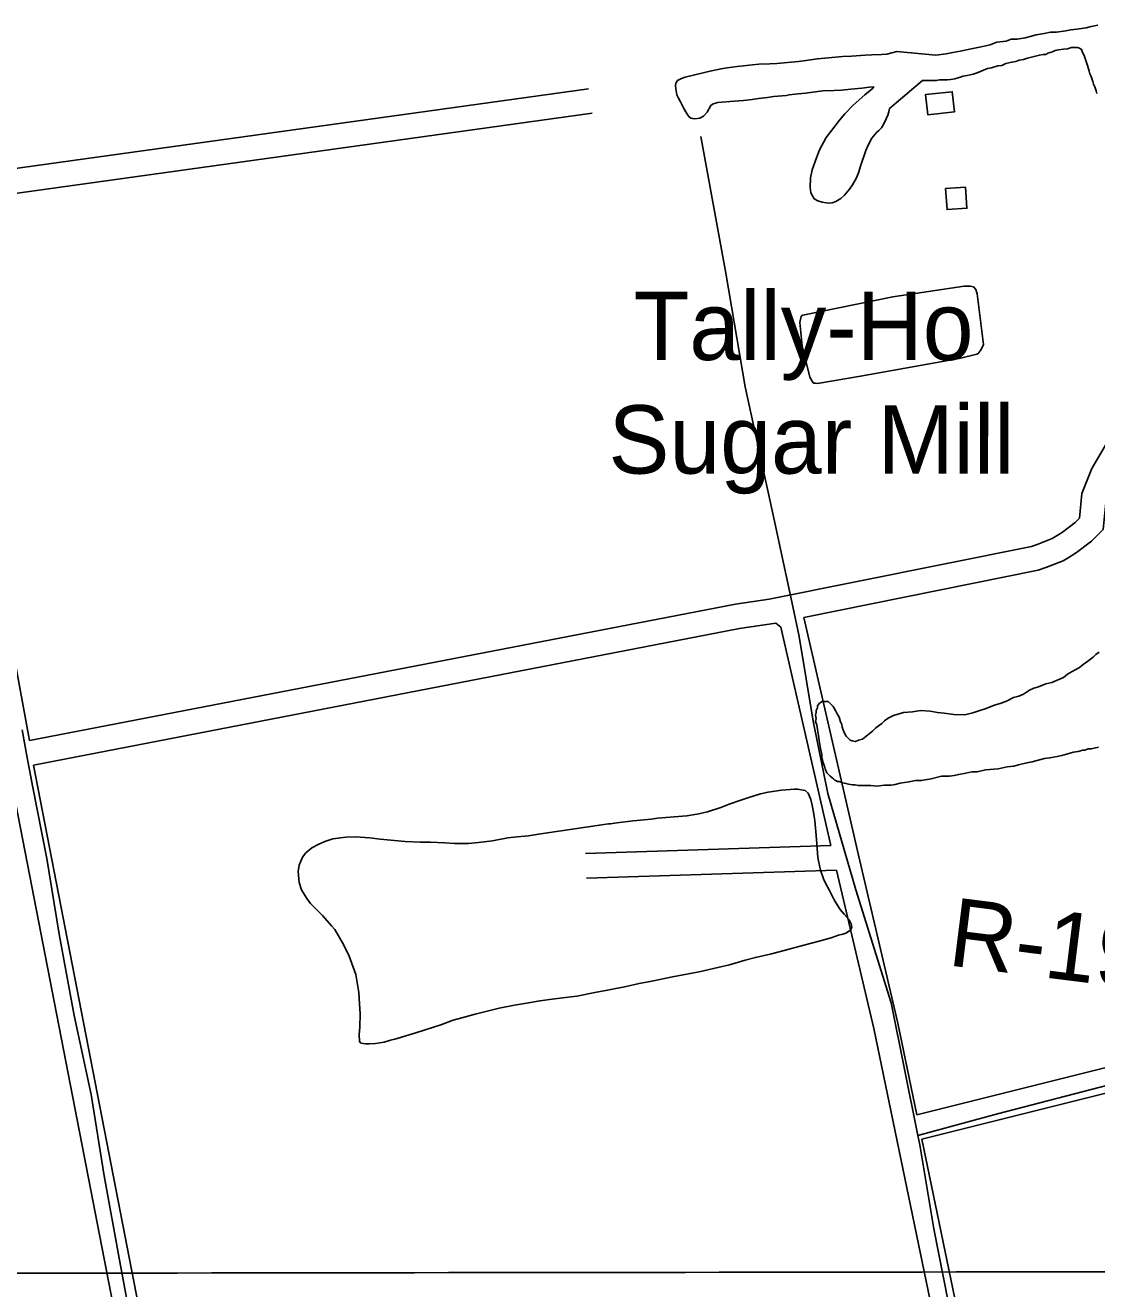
# Model space of a CAD drawing. Extents: x 3324125 to 3362000, y 600753 to 626151.
# Drawn here: x 3330131 to 3331432, y 618241 to 619776 of the extents above; entities that cross this region are included whole.
import ezdxf

# ---------------------------------------------------------------- set-up
doc = ezdxf.new("R2010")
doc.units = 0
for name, color, linetype in [('V-BLDG-IDEN', 7, 'Continuous'), ('V-BLDG-OTLN', 7, 'Continuous'), ('V-DTCH-CNTR', 7, 'Continuous'), ('V-GRID-MAJR', 7, 'Continuous'), ('V-RIVR-RANG-IDEN', 7, 'Continuous'), ('V-ROAD-CNTR', 7, 'Continuous'), ('V-SITE-VEGE', 7, 'Continuous'), ('V-TOPO-SHOR', 7, 'Continuous')]:
    doc.layers.add(name, color=color, linetype=linetype)

msp = doc.modelspace()

# ---------------------------------------------------------------- linework, layer by layer
at = {"layer": 'V-BLDG-OTLN'}
for points in [[(3331224.6, 619691.7), (3331257, 619695.1), (3331259.6, 619670.5), (3331227.2, 619667.1)], [(3331248.9, 619577.3), (3331273.1, 619578.9), (3331274.8, 619553.5), (3331250.7, 619551.8)]]:
    msp.add_lwpolyline(points, close=True, dxfattribs=at)
at = {"layer": 'V-DTCH-CNTR'}
for points in [[(3331258.3, 618192.4), (3331234.4, 618313.6), (3331217.5, 618415.7), (3331215.2, 618426.9), (3331182.8, 618587.9), (3331139.8, 618725.2), (3331105.6, 618842.5), (3331087.8, 618930.2), (3331070.9, 619033.1), (3331063.4, 619069.4), (3331040.2, 619177.1), (3331005.4, 619336.6), (3330981.6, 619474.6), (3330951.6, 619640.5)], [(3330126.9, 618919.7), (3330132.5, 618888.2), (3330139.8, 618849.5), (3330156.8, 618763.4), (3330171.7, 618671.3), (3330189.8, 618572.8), (3330210.7, 618476.7), (3330226.4, 618377.8), (3330245.6, 618273.4), (3330271.8, 618131.8), (3330298.4, 618004.6), (3330321.7, 617904.1), (3330351.9, 617768.1), (3330376.9, 617628.9), (3330397.7, 617531.6), (3330416.6, 617429.1), (3330430.7, 617337.1), (3330433, 617316.3), (3330443.5, 617274), (3330455.8, 617210.2), (3330473.6, 617123.7), (3330496.5, 617039.5), (3330502, 617020.8)], [(3331215.2, 618426.9), (3331311.8, 618453.3), (3331425.9, 618482.8), (3331525.6, 618508.5), (3331632.5, 618535.7), (3331741.9, 618566), (3331832, 618591.7), (3331966.9, 618626.7), (3332061.8, 618649.2)]]:
    msp.add_lwpolyline(points, dxfattribs=at)
at = {"layer": 'V-GRID-MAJR'}
msp.add_spline([(3328217.9, 618256.9), (3333482.8, 618264.2), (3338747.8, 618272.2), (3344012.7, 618281.1), (3349277.7, 618290.6), (3354542.6, 618301), (3359807.6, 618312.1)], degree=3, dxfattribs=at)
at = {"layer": 'V-ROAD-CNTR'}
msp.add_line((3330056.8, 619334.1), (3330135.7, 618906.7), dxfattribs=at)
for points in [[(3330007.1, 619586.3), (3330815, 619698.5)], [(3330012.9, 619556.8), (3330819.2, 619668.8)], [(3331481.1, 619278.3), (3331444.2, 619267.6), (3331426.5, 619237.3), (3331414.5, 619206.9), (3331411.5, 619176.8), (3331406.4, 619171.7), (3331390.9, 619159.9), (3331388.4, 619158.4)], [(3331484.1, 619247.9), (3331464.1, 619242.1), (3331453.5, 619224.2), (3331443.9, 619199.8), (3331440.2, 619163.2), (3331426.2, 619149.1), (3331407.8, 619135.1), (3331397.6, 619128.8)], [(3331388.4, 619158.4), (3331378.2, 619152.2), (3331360.1, 619145), (3331353.2, 619142.6), (3331034.6, 619078.4)], [(3331397.6, 619128.8), (3331391.6, 619125.2), (3331370.5, 619116.9), (3331361.2, 619113.6), (3331076.7, 619056.3)], [(3331034.6, 619078.4), (3330993.6, 619072.4), (3330135.7, 618906.7)], [(3331142.9, 618767.3), (3331076.7, 619056.3)], [(3331109.4, 618779.1), (3331048.6, 619044.5), (3331042.6, 619049.2), (3330998.6, 619042.8), (3330140.4, 618877)], [(3330111, 618871.3), (3330427.3, 617243.1), (3330469.2, 617043)], [(3330140.4, 618877), (3330456.7, 617249.1), (3330497.7, 617053.5)], [(3331109.4, 618779.1), (3330811.3, 618769.4)], [(3331214, 618452), (3331191, 618563.5), (3331142.9, 618767.3)], [(3331116.3, 618749.3), (3330812.3, 618739.5)], [(3331399.7, 617387.8), (3331396.8, 617421), (3331161.7, 618557), (3331116.3, 618749.3)], [(3331214, 618452), (3331723.1, 618579.1)], [(3331220.1, 618422.6), (3331725.4, 618548.8)], [(3331428.8, 617398.6), (3331426.5, 617425.3), (3331220.1, 618422.6)]]:
    msp.add_lwpolyline(points, dxfattribs=at)
at = {"layer": 'V-SITE-VEGE'}
for points in [[(3331055.5, 619690.5), (3331039.7, 619689.1), (3331032.3, 619688), (3331021.3, 619686.7), (3331013.9, 619685.6), (3331003.4, 619684.3), (3330991.9, 619683.4), (3330972.1, 619682.1), (3330966.4, 619680.2), (3330963.5, 619678.3), (3330959.2, 619670), (3330954.7, 619665.2), (3330950.4, 619663.1), (3330944.2, 619662.1), (3330941.5, 619662.5), (3330939.3, 619663.1), (3330937.2, 619664.5), (3330935.5, 619666.6), (3330930.9, 619674.8), (3330928.4, 619679.5), (3330926.8, 619682.6), (3330924.2, 619687.3), (3330922.4, 619691.2), (3330920.9, 619698.6), (3330920.6, 619702.7), (3330921.2, 619705.4), (3330923.1, 619708.5), (3330927.8, 619711.2), (3330932.5, 619712.9), (3330944.1, 619715.7), (3330955.8, 619718.2), (3330964.4, 619720.3), (3330976, 619722.9), (3330983.6, 619724), (3330995.7, 619725.5), (3331003.3, 619726.6), (3331014.1, 619727.9), (3331022.1, 619728.4), (3331035.3, 619729.1), (3331043.9, 619729.5), (3331070.3, 619731.6), (3331079.2, 619732.9), (3331093, 619735.2), (3331102.2, 619735.9), (3331123.6, 619737.9), (3331134.6, 619738.4), (3331151.3, 619739.6), (3331159.3, 619740), (3331170.8, 619740.3), (3331177.4, 619740.8), (3331189.4, 619743.9), (3331236.9, 619739.6), (3331249.7, 619741.1), (3331257.7, 619742.7), (3331266.4, 619744.2), (3331284, 619748.1), (3331292, 619749.6), (3331303.1, 619751.9), (3331311.1, 619755.1), (3331322.3, 619756.6), (3331328.7, 619758.9), (3331335.8, 619758.9), (3331345.4, 619760.4), (3331351.8, 619762), (3331359, 619764.3), (3331368.5, 619765.8), (3331376.5, 619767.4), (3331383.7, 619767.3), (3331394.8, 619768.9), (3331401.2, 619770.4), (3331408.4, 619771.2), (3331419.6, 619772.7), (3331425.9, 619774.2), (3331433.9, 619775.8)], [(3331432.6, 619693), (3331431.8, 619696.1), (3331430.3, 619700.9), (3331428.7, 619704.1), (3331427.9, 619707.3), (3331425.6, 619713.7), (3331424, 619716.9), (3331423.2, 619720.1), (3331421.6, 619725.7), (3331417.7, 619737.7), (3331414.6, 619744), (3331413.8, 619746.4), (3331411.4, 619748), (3331409.1, 619748.9), (3331401.9, 619748.9), (3331397.1, 619747.3), (3331392.3, 619746.6), (3331385.9, 619745.8), (3331381.9, 619745.1), (3331378.8, 619743.5), (3331373.2, 619741.9), (3331370.8, 619740.3), (3331367.6, 619740.4), (3331362.8, 619739.6), (3331356.4, 619738), (3331351.6, 619736.5), (3331348.4, 619735.7), (3331343.6, 619734.1), (3331338.1, 619733.4), (3331334.1, 619731.8), (3331329.3, 619731.1), (3331322.1, 619729.5), (3331317.3, 619727.1), (3331312.5, 619726.4), (3331304.5, 619724), (3331299.8, 619723.3), (3331287, 619717.8), (3331282.2, 619716.2), (3331275, 619714.7), (3331270.2, 619713.9), (3331265.4, 619712.3), (3331259.9, 619710.8), (3331255.1, 619710), (3331251.1, 619709.3), (3331241.5, 619709.3), (3331237.5, 619708.5), (3331220.8, 619708.7), (3331180.8, 619674.6), (3331180, 619670.5), (3331178.6, 619666.6), (3331174.7, 619657.7), (3331172.1, 619653.3), (3331170.8, 619651.3), (3331167.8, 619648.1), (3331165.3, 619645.7), (3331161.2, 619641.1), (3331159.4, 619638.8), (3331154.7, 619630.3), (3331151.9, 619623.5), (3331146, 619605.9), (3331143, 619596.4), (3331140.5, 619590.4), (3331135.9, 619581.8), (3331132.2, 619576.6), (3331125.8, 619569.3), (3331121.7, 619565.4), (3331115.6, 619561.6), (3331111.1, 619560.1), (3331106.5, 619559.7), (3331098.7, 619560.7), (3331093.7, 619562.3), (3331089, 619565), (3331085.2, 619572.3), (3331084.3, 619578.7), (3331084.7, 619590.3), (3331086.7, 619600), (3331092.1, 619614.8), (3331095.8, 619624.4), (3331103.9, 619639.5), (3331110.5, 619648.2), (3331119.8, 619660.6), (3331126.2, 619668.1), (3331136.2, 619678.2), (3331143.8, 619685.3), (3331150.6, 619691.1), (3331159.8, 619698.4), (3331161.6, 619701.1), (3331156.5, 619700.6), (3331147.2, 619699.3), (3331133.8, 619698), (3331122.5, 619697.1), (3331113.4, 619696.6), (3331099.6, 619696.1), (3331078.6, 619693.1), (3331069.7, 619692.4), (3331058.8, 619691.1), (3331055.5, 619690.5)], [(3331095.4, 618906.6), (3331094.6, 618912.9), (3331093.1, 618920.1), (3331092.3, 618925.7), (3331090.7, 618929.7), (3331091.6, 618933.7), (3331090.8, 618937.7), (3331091.6, 618940.8), (3331091.6, 618943.2), (3331093.2, 618946.4), (3331093.2, 618948.8), (3331095.7, 618952), (3331098.9, 618954.3), (3331106, 618954.3), (3331112.4, 618947.9), (3331115.5, 618942.3), (3331117.1, 618939.1), (3331119.4, 618935.1), (3331121, 618929.5), (3331122.6, 618926.3), (3331123.3, 618923.1), (3331125.7, 618916.7), (3331128.1, 618911.9), (3331132.8, 618907.1), (3331135.2, 618906.3), (3331139.2, 618905.5), (3331143.2, 618907.1), (3331147.9, 618908.6), (3331160, 618918.1), (3331164, 618922.1), (3331171.2, 618927.6), (3331174.4, 618930.8), (3331179.2, 618933.9), (3331185.6, 618937.1), (3331197.5, 618941), (3331208.7, 618941.7), (3331218.3, 618943.2), (3331230.2, 618942.3), (3331239, 618940.7), (3331246.9, 618939.8), (3331258.9, 618938.2), (3331272.4, 618938.1), (3331282, 618940.4), (3331289.1, 618942.8), (3331297.1, 618945.1), (3331308.3, 618949.8), (3331316.3, 618952.1), (3331322.7, 618954.5), (3331331.5, 618959.2), (3331337.9, 618960.8), (3331343.4, 618963.1), (3331350.6, 618967.8), (3331356.2, 618970.2), (3331361.8, 618971.8), (3331370.6, 618975.7), (3331377.8, 618977.2), (3331383.4, 618979.6), (3331392.2, 618983.5), (3331397, 618987.5), (3331402.6, 618990.6), (3331411.4, 618995.3), (3331416.2, 618999.3), (3331421.8, 619003.2), (3331428.2, 619008), (3331431.4, 619011.1), (3331435.4, 619014.3)], [(3331434.6, 618898.8), (3331425.9, 618896.5), (3331421.9, 618896.5), (3331417.9, 618894.9), (3331415.5, 618894.9), (3331409.9, 618893.4), (3331404.3, 618892.6), (3331390, 618888.7), (3331384.4, 618887.2), (3331375.6, 618885.6), (3331369.2, 618884.9), (3331362.8, 618883.3), (3331354.1, 618881), (3331347.7, 618879.5), (3331337.3, 618877.1), (3331331.7, 618875.6), (3331323.8, 618874.8), (3331312.6, 618872.5), (3331297.4, 618871), (3331287.1, 618868.7), (3331280.7, 618868.7), (3331273.5, 618867.2), (3331264.8, 618865.6), (3331259.2, 618864.1), (3331253.6, 618863.3), (3331244, 618863.4), (3331231.3, 618860.3), (3331219.3, 618858), (3331212.1, 618858), (3331204.2, 618856.5), (3331193.8, 618855), (3331187.4, 618853.4), (3331182.6, 618852.6), (3331174.7, 618852.7), (3331165.1, 618851.2), (3331157.9, 618852), (3331142.8, 618852.1), (3331138.8, 618852.9), (3331135.6, 618852.9), (3331130.9, 618853.8), (3331127.7, 618854.6), (3331123.7, 618855.4), (3331119.7, 618857), (3331117.3, 618857), (3331114.2, 618858.7), (3331112.6, 618860.3), (3331108.6, 618863.5), (3331104.7, 618867.5), (3331102.3, 618872.3), (3331101.5, 618875.5), (3331100, 618879.5), (3331098.4, 618886.6), (3331098.4, 618889.8), (3331096.9, 618897), (3331095.4, 618906.6)], [(3331082, 618843), (3331084.9, 618835.2), (3331086.6, 618828.4), (3331088.7, 618817.1), (3331090, 618809.1), (3331091.2, 618795.9), (3331091.8, 618786.6), (3331093.6, 618764.6), (3331096, 618752.8), (3331097, 618749.1), (3331100.6, 618738.8), (3331103.3, 618732.5), (3331107.7, 618724.5), (3331110, 618719.7), (3331113.6, 618713.2), (3331115.9, 618709), (3331120.9, 618701.5), (3331125.4, 618695.9), (3331131.7, 618688.8), (3331134.2, 618684.2), (3331135, 618679.5), (3331133.4, 618676.4), (3331127.6, 618672.9), (3331124, 618671.6), (3331118.8, 618670.1), (3331109.6, 618667.2), (3331093.7, 618662.7), (3331085.7, 618660.6), (3331072.3, 618656.8), (3331046.6, 618650), (3331035.7, 618647.3), (3331017.8, 618643.2), (3331005.4, 618639.9), (3330986.1, 618634.4), (3330972.1, 618631), (3330949.5, 618625.9), (3330916.9, 618619.5), (3330891.8, 618614.5), (3330876.4, 618611.6), (3330860.5, 618608.1), (3330837.9, 618603.5), (3330822.7, 618600.7), (3330800.6, 618596.2), (3330786.8, 618594.5), (3330767.7, 618592), (3330756.1, 618590.5), (3330737.2, 618587.3), (3330725.1, 618585.4), (3330706.5, 618581.5), (3330677.1, 618574.1), (3330661.2, 618569.9), (3330650.6, 618566.9), (3330635.3, 618561.5), (3330605.3, 618551.8), (3330579.4, 618544), (3330574.2, 618542.7), (3330566.8, 618540.2), (3330556.3, 618538.7), (3330548.7, 618538.4), (3330544, 618538.4), (3330538.4, 618539.2), (3330536.5, 618541), (3330536.1, 618549.7), (3330537, 618558.5), (3330537.3, 618574.8), (3330536.8, 618586.8), (3330535.9, 618600.6), (3330532.1, 618622.6), (3330524.3, 618644.6), (3330517.2, 618659), (3330506.5, 618677), (3330502.6, 618681.8), (3330491.6, 618694), (3330477.1, 618708.6), (3330472.5, 618714.7), (3330466, 618725.4), (3330463.3, 618734.3), (3330462.3, 618747.6), (3330463.3, 618755.5), (3330467.4, 618765.2), (3330471.3, 618770.2), (3330478.9, 618776.4), (3330486.6, 618780.6), (3330494.7, 618784.2), (3330504.3, 618787.3), (3330520.2, 618789.3), (3330531.5, 618789.8), (3330549.3, 618788.7), (3330561.8, 618787.1), (3330592, 618784.2), (3330610.3, 618783.3), (3330622.9, 618783.2), (3330640.2, 618782.5), (3330652, 618781.7), (3330669.3, 618781.8), (3330681.2, 618782.8), (3330698.3, 618784.9), (3330717.1, 618788.4), (3330728.4, 618789.7), (3330742.2, 618791), (3330754.1, 618793.1)], [(3330754.1, 618793.1), (3330839.2, 618805.5), (3330841.7, 618805.7), (3330849.3, 618806.8), (3330869, 618809.2), (3330890.9, 618811.4), (3330898.9, 618812.3), (3330934.6, 618815.2), (3330948.8, 618817.6), (3330959.5, 618820.3), (3330975.9, 618825.4), (3330986, 618829.4), (3331000, 618834.4), (3331009.8, 618837.6), (3331023.8, 618841.8), (3331033.1, 618844.1), (3331049.6, 618846.5), (3331065.4, 618847.8), (3331068.9, 618847.7), (3331078.2, 618845.9), (3331082, 618843)]]:
    msp.add_lwpolyline(points, dxfattribs=at)
at = {"layer": 'V-TOPO-SHOR'}
msp.add_lwpolyline([(3331265.4, 619370.9), (3331145.5, 619349.4), (3331093, 619340.6), (3331090.7, 619341.1), (3331088.9, 619341.1), (3331088, 619341.5), (3331083.9, 619348.4), (3331074.6, 619386.3), (3331071.6, 619414.5), (3331073.5, 619422.3), (3331075.3, 619423.6), (3331184.8, 619445.7), (3331271.5, 619458.8), (3331278.8, 619458.8), (3331282.9, 619457.8), (3331285.6, 619454.6), (3331287.4, 619449.6), (3331294.7, 619388), (3331291.9, 619381.7), (3331288.3, 619377.1), (3331286.9, 619376.2), (3331265.4, 619370.9)], dxfattribs=at)

# ---------------------------------------------------------------- texts
at = {"layer": 'V-BLDG-IDEN'}
for s, p in [('Tally-Ho', (3330869.6, 619369.1)), ('Sugar Mill', (3330839.2, 619231.1))]:
    msp.add_text(s, height=83, rotation=359.9873, dxfattribs=at).set_placement(p)
at = {"layer": 'V-RIVR-RANG-IDEN'}
msp.add_text('R-194.98', height=83, rotation=352.8427, dxfattribs=at).set_placement((3331250.1, 618633.8))

doc.saveas('drawing.dxf')
